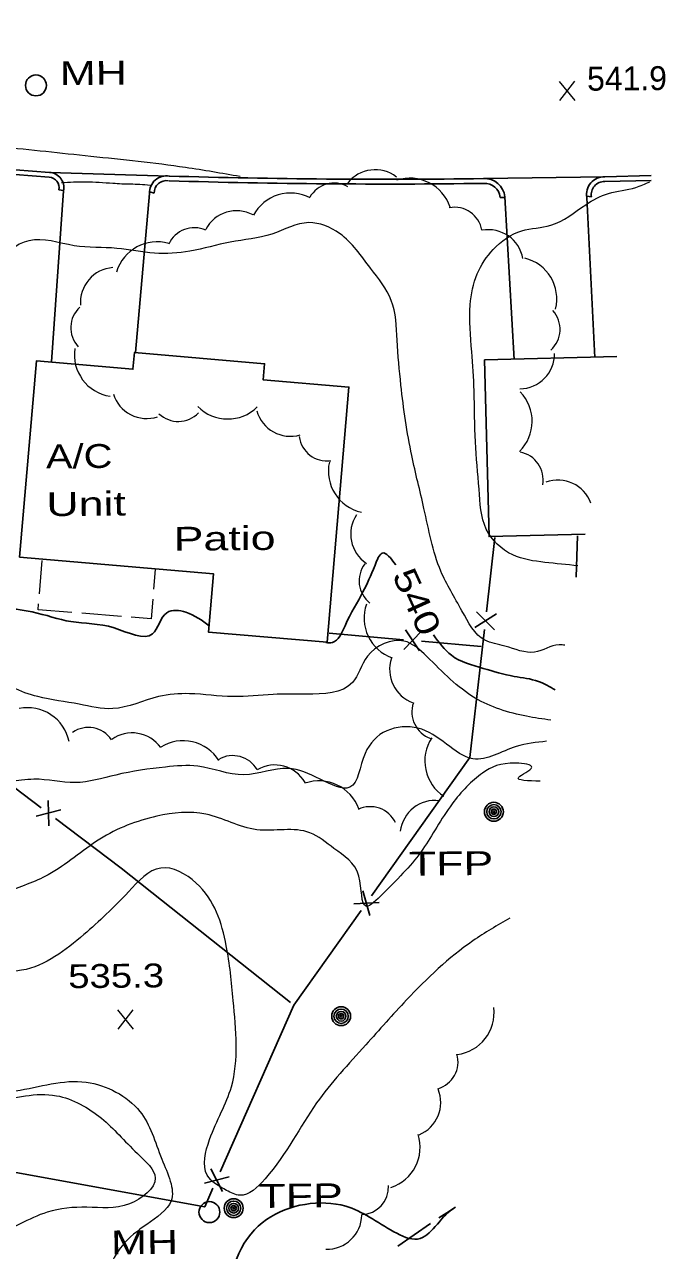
# Model space of a CAD drawing. Extents: x 2361708 to 2370558, y 6977955 to 6991887.
# Drawn here: x 2366752.4 to 2366881.3, y 6983523.9 to 6983770.4 of the extents above; entities that cross this region are included whole.
import ezdxf
from ezdxf.enums import TextEntityAlignment as Align

# ---------------------------------------------------------------- set-up
doc = ezdxf.new("R2010")
doc.units = 0
doc.header["$LTSCALE"] = 1.9
for name, color, linetype, lineweight in [('11', 7, 'Continuous', 25), ('12', 7, 'Continuous', 25), ('14', 7, 'Continuous', 13), ('17', 7, 'Continuous', 25), ('2', 7, 'Continuous', 25), ('20', 7, 'Continuous', 25), ('29', 7, 'Continuous', 13), ('31', 7, 'Continuous', 13), ('35', 7, 'Continuous', 13)]:
    doc.layers.add(name, color=color, linetype=linetype, lineweight=lineweight)

msp = doc.modelspace()

# ---------------------------------------------------------------- linework, layer by layer
at = {"layer": '11'}
msp.add_lwpolyline([(2366751.426, 6983663.277), (2366790.399, 6983659.958), (2366789.401, 6983648.238), (2366813.261, 6983646.205), (2366817.633, 6983697.479), (2366800.389, 6983698.955), (2366800.668, 6983702.167), (2366774.505, 6983704.419), (2366774.217, 6983701.066), (2366754.82, 6983702.731)], close=True, dxfattribs=at)
msp.add_lwpolyline([(2366871.488, 6983703.612), (2366844.893, 6983702.939), (2366845.801, 6983667.416), (2366865.107, 6983667.909)], dxfattribs=at)
at = {"layer": '12'}
msp.add_line((2366834.055, 6983529.327), (2366827.468, 6983524.784), dxfattribs=at)
msp.add_lwpolyline([(2366839.064, 6983532.635), (2366837.294, 6983531.498), (2366835.704, 6983530.463)], dxfattribs=at)
at = {"layer": '14'}
for p, q in [((2366755.416, 6983655.914), (2366755.942, 6983662.62)), ((2366778.691, 6983660.817), (2366778.378, 6983656.833)), ((2366771.88, 6983651.381), (2366763.904, 6983652.015))]:
    msp.add_line(p, q, dxfattribs=at)
for points in [[(2366761.912, 6983652.177), (2366755.157, 6983652.702), (2366755.255, 6983653.923)], [(2366778.218, 6983654.842), (2366777.905, 6983650.898), (2366773.872, 6983651.22)]]:
    msp.add_lwpolyline(points, dxfattribs=at)
at = {"layer": '17'}
for p, q in [((2366846.963, 6983667.206), (2366845.275, 6983652.3)), ((2366863.61, 6983667.595), (2366863.349, 6983659.282)), ((2366842.945, 6983649.147), (2366847.269, 6983651.878)), ((2366843.295, 6983652.321), (2366846.919, 6983648.695)), ((2366831.839, 6983644.431), (2366828.998, 6983648.695)), ((2366813.684, 6983647.989), (2366828.627, 6983646.691)), ((2366828.657, 6983644.711), (2366832.191, 6983648.415)), ((2366832.211, 6983646.375), (2366844.201, 6983645.329)), ((2366743.809, 6983621.933), (2366755.776, 6983612.886)), ((2366757.3, 6983609.27), (2366757.162, 6983614.389)), ((2366754.752, 6983611.196), (2366759.71, 6983612.463)), ((2366820.457, 6983596.191), (2366821.865, 6983591.264)), ((2366818.602, 6983593.583), (2366823.72, 6983593.872)), ((2366789.878, 6983540.327), (2366792.242, 6983535.789)), ((2366788.585, 6983537.405), (2366793.534, 6983538.712))]:
    msp.add_line(p, q, dxfattribs=at)
for points in [[(2366844.869, 6983648.726), (2366841.973, 6983623.037), (2366822.177, 6983595.207)], [(2366758.647, 6983610.713), (2366771.832, 6983600.758), (2366805.91, 6983573.761)], [(2366820.095, 6983592.277), (2366806.555, 6983573.247), (2366791.764, 6983539.725)], [(2366790.305, 6983536.431), (2366788.641, 6983532.655), (2366733.673, 6983542.672)]]:
    msp.add_lwpolyline(points, dxfattribs=at)
at = {"layer": '2'}
for p, q in [((2366781.528, 6983739.897), (2366757.45, 6983740.638)), ((2366869.094, 6983739.771), (2366844.666, 6983739.378)), ((2366878.402, 6983739.989), (2366869.094, 6983739.771)), ((2366878.411, 6983739.03), (2366869.112, 6983738.811)), ((2366760.255, 6983736.935), (2366757.812, 6983702.549)), ((2366759.313, 6983737.135), (2366760.255, 6983736.975)), ((2366777.541, 6983736.419), (2366774.746, 6983704.401)), ((2366778.501, 6983736.458), (2366777.588, 6983736.749)), ((2366848.012, 6983735.62), (2366848.972, 6983735.589)), ((2366848.971, 6983735.699), (2366850.823, 6983703.025)), ((2366866.392, 6983735.725), (2366865.441, 6983735.846)), ((2366865.443, 6983735.566), (2366867.039, 6983703.4))]:
    msp.add_line(p, q, dxfattribs=at)
for centre, radius, start, end in [((2366836.933, 6984859.981), 1123.122, 260.32788, 265.93829), ((2366836.933, 6984859.981), 1122.162, 260.32788, 265.93829), ((2366757.244, 6983737.567), 2.117, 348.14792, 86.15841), ((2366757.244, 6983737.567), 3.077, 348.14792, 86.15841), ((2366780.942, 6983736.544), 3.404, 80.07877, 182.1094), ((2366825.43, 6985239.846), 1500.591, 268.32349, 270.73449), ((2366869.006, 6983736.16), 3.612, 88.6053, 189.46421), ((2366780.942, 6983736.544), 2.444, 80.07877, 182.1094), ((2366825.43, 6985239.846), 1501.551, 268.32349, 270.73449), ((2366844.975, 6983735.381), 4.009, 4.55432, 94.41329), ((2366844.975, 6983735.381), 3.049, 4.55432, 94.41329), ((2366869.006, 6983736.16), 2.652, 88.6053, 189.46421)]:
    msp.add_arc(centre, radius, start, end, dxfattribs=at)
at = {"layer": '20'}
for centre, radius in [((2366754.713, 6983758.123), 2.1), ((2366846.778, 6983612.102), 1.9), ((2366846.778, 6983612.102), 1.442), ((2366846.778, 6983612.102), 0.973), ((2366846.778, 6983612.102), 0.539), ((2366846.778, 6983612.102), 0.192), ((2366816.067, 6983570.998), 1.9), ((2366816.067, 6983570.998), 1.442), ((2366816.067, 6983570.998), 0.973), ((2366816.067, 6983570.998), 0.539), ((2366816.067, 6983570.998), 0.192), ((2366789.581, 6983531.614), 2.1), ((2366794.464, 6983532.4), 1.9), ((2366794.464, 6983532.4), 1.442), ((2366794.464, 6983532.4), 0.973), ((2366794.464, 6983532.4), 0.539), ((2366794.464, 6983532.4), 0.192)]:
    msp.add_circle(centre, radius, dxfattribs=at)
at = {"layer": '29'}
for centre, radius, start, end in [((2366822.916, 6983734.121), 7.055, 52.38833, 142.38833), ((2366814.665, 6983732.857), 5.638, 60.58889, 150.58889), ((2366829.91, 6983731.025), 8.462, 18.00387, 108.00387), ((2366805.882, 6983728.032), 8.462, 61.91748, 151.91748), ((2366795.078, 6983725.868), 7.055, 62.08292, 152.08292), ((2366838.837, 6983727.986), 5.638, 10.39823, 100.39823), ((2366786.541, 6983723.87), 5.638, 65.57129, 155.57129), ((2366845.679, 6983722.054), 7.055, 10.39823, 100.39823), ((2366779.04, 6983718.224), 8.462, 73.61468, 163.61468), ((2366850.974, 6983715.175), 8.462, 346.2323, 76.2323), ((2366770.697, 6983714.463), 7.055, 94.34818, 184.34818), ((2366767.354, 6983709.4), 5.638, 132.54214, 222.54214), ((2366854.446, 6983709.104), 5.638, 311.87807, 41.87807), ((2366770.897, 6983703.996), 8.462, 171.45439, 261.45439), ((2366851.928, 6983704.189), 7.055, 270.4573, 0.4573), ((2366776.993, 6983698.216), 7.055, 197.67282, 287.67282), ((2366846.008, 6983690.592), 8.462, 314.31729, 44.31729), ((2366793.279, 6983699.523), 8.462, 224.50512, 314.50512), ((2366783.329, 6983696.213), 5.638, 226.37091, 316.37091), ((2366805.897, 6983694.638), 7.055, 195.95919, 285.95919), ((2366813.231, 6983688.264), 5.638, 187.60075, 277.60075), ((2366851.05, 6983678.837), 5.638, 349.72468, 79.72468), ((2366821.966, 6983680.589), 8.462, 167.56341, 257.56341), ((2366859.634, 6983671.728), 7.055, 19.90738, 109.90738), ((2366825.053, 6983667.929), 7.055, 146.58476, 236.58476), ((2366825.317, 6983658.517), 5.638, 142.31188, 232.31188), ((2366829.142, 6983651.03), 8.462, 160.53118, 250.53118), ((2366832.877, 6983640.69), 7.055, 161.01121, 251.01121), ((2366835.927, 6983632.164), 5.638, 161.01121, 251.01121), ((2366753.077, 6983624.547), 8.462, 11.67391, 101.67391), ((2366765.255, 6983623.403), 5.638, 34.22923, 124.22923), ((2366774.051, 6983620.897), 7.055, 35.501, 125.501), ((2366784.303, 6983617.919), 8.462, 31.96373, 121.96373), ((2366841.354, 6983622.302), 8.462, 146.82001, 236.82001), ((2366794.284, 6983617.744), 5.638, 30.01109, 120.01109), ((2366802.72, 6983614.452), 7.055, 30.01109, 120.01109), ((2366811.617, 6983609.84), 8.462, 19.50571, 109.50571), ((2366834.97, 6983607.325), 7.055, 83.06463, 173.06463), ((2366821.911, 6983607.49), 5.638, 25.50781, 115.50781), ((2366838.362, 6983571.704), 8.462, 276.91624, 6.91624), ((2366833.936, 6983561.845), 5.638, 285.96986, 15.96986), ((2366829.037, 6983553.671), 7.055, 292.45055, 22.45055), ((2366823.476, 6983544.623), 8.462, 288.00847, 18.00847), ((2366819.983, 6983536.743), 5.638, 272.01675, 2.01675), ((2366813.182, 6983531.199), 7.055, 268.54102, 358.54102)]:
    msp.add_arc(centre, radius, start, end, dxfattribs=at)
at = {"layer": '31'}
for p, q in [((2366863.087, 6983755.094), (2366859.971, 6983758.944)), ((2366860.008, 6983755.065), (2366863.05, 6983758.974)), ((2366774.31, 6983568.41), (2366771.193, 6983572.26)), ((2366771.23, 6983568.381), (2366774.273, 6983572.29))]:
    msp.add_line(p, q, dxfattribs=at)
at = {"layer": '31', "lineweight": 25}
for points in [[(2366827.064, 6983661.747), (2366824.332, 6983664.101), (2366822.885, 6983661.677), (2366820.455, 6983656.304), (2366816.86, 6983649.499), (2366814.302, 6983646.135), (2366813.022, 6983646.102)], [(2366789.509, 6983649.489), (2366784.843, 6983652.215), (2366781.053, 6983652.118), (2366778.174, 6983647.881), (2366770.442, 6983649.067), (2366761.759, 6983650.334), (2366753.961, 6983652.261), (2366747.757, 6983653.612), (2366742.809, 6983656.604), (2366734.911, 6983659.47), (2366729.477, 6983655.687), (2366726.12, 6983647.985), (2366719.2, 6983644.82), (2366710.639, 6983643.758), (2366699.079, 6983642.658), (2366694.648, 6983643.885)], [(2366859.105, 6983636.6), (2366855.718, 6983638.308), (2366850.849, 6983639.322), (2366844.633, 6983640.923), (2366838.238, 6983643.552), (2366834.639, 6983647.658)], [(2366838.686, 6983532.361), (2366838.477, 6983532.229), (2366831.444, 6983526.202), (2366826.66, 6983527.676), (2366816.981, 6983532.805), (2366808.817, 6983533.177), (2366795.511, 6983523.29), (2366794.748, 6983515.153), (2366804.244, 6983513.522), (2366807.862, 6983511.667), (2366805.953, 6983508.329), (2366801.068, 6983503.632), (2366794.607, 6983495.26), (2366786.548, 6983487.793)]]:
    msp.add_spline(points, degree=3, dxfattribs=at)
at = {"layer": '35'}
for points in [[(2366795.74, 6983739.802), (2366784.772, 6983741.618), (2366765.76, 6983743.847), (2366747.59, 6983745.754), (2366728.399, 6983747.912), (2366712.125, 6983750.377), (2366697.94, 6983751.832), (2366682.366, 6983755.404), (2366671.397, 6983760.49), (2366665.82, 6983767.497), (2366668.009, 6983771.788), (2366673.177, 6983775.238), (2366681.905, 6983776.521), (2366694.687, 6983776.332), (2366708.267, 6983775.382), (2366723.293, 6983774.854), (2366736.776, 6983774.553), (2366754.313, 6983773.84), (2366769.582, 6983774.095), (2366778.547, 6983773.57), (2366782.742, 6983774.2), (2366781.845, 6983774.902), (2366780.078, 6983775.605), (2366775.42, 6983776.351), (2366772.614, 6983777.014), (2366770.831, 6983777.407)], [(2366759.849, 6983738.591), (2366764.678, 6983738.756), (2366770.191, 6983738.469), (2366773.713, 6983738.313), (2366775.593, 6983738.271), (2366777.675, 6983738.08)], [(2366863.668, 6983661.545), (2366857.021, 6983662.242), (2366850.556, 6983663.75), (2366845.257, 6983668.93), (2366843.8, 6983676.927), (2366843.05, 6983686.47), (2366842.802, 6983696.729), (2366842.317, 6983704.584), (2366842.027, 6983714.042), (2366843.448, 6983720.256), (2366846.652, 6983725.136), (2366852.376, 6983728.881), (2366858.216, 6983729.997), (2366865.247, 6983734.134), (2366869.795, 6983736.417), (2366875.294, 6983737.619), (2366878.123, 6983738.766)], [(2366861.07, 6983645.58), (2366859.889, 6983645.659), (2366854.963, 6983644.171), (2366849, 6983645.425), (2366844.99, 6983646.577), (2366840.363, 6983652.473), (2366836.117, 6983660.473), (2366832.726, 6983673.091), (2366830.266, 6983683.698), (2366828.1, 6983697.858), (2366827.334, 6983706.922), (2366826.158, 6983714.891), (2366821.966, 6983721.391), (2366815.77, 6983728.342), (2366809.598, 6983730.534), (2366802.16, 6983728.253), (2366793.785, 6983726.613), (2366785.672, 6983724.796), (2366778.545, 6983724.408), (2366770.996, 6983725.366), (2366762.41, 6983725.905), (2366753.29, 6983726.908), (2366746.93, 6983721.677), (2366745.677, 6983713.554), (2366744.422, 6983705.642), (2366739.441, 6983701.535), (2366734.206, 6983700.945), (2366732.347, 6983700.877)], [(2366858.233, 6983630.522), (2366853.315, 6983631.295), (2366843.03, 6983634.948), (2366833.3, 6983643.315), (2366828.7, 6983646.422), (2366821.359, 6983643.351), (2366818.339, 6983638.063), (2366809.061, 6983635.714), (2366802.371, 6983635.69), (2366794.315, 6983635.244), (2366785.589, 6983635.841), (2366779.374, 6983635.242), (2366770.166, 6983632.834), (2366763.418, 6983633.72), (2366755.073, 6983635.24), (2366745.884, 6983640.283), (2366740.135, 6983646.489), (2366736.095, 6983646.42), (2366734.954, 6983642.409), (2366733.616, 6983635.846)], [(2366857.373, 6983626.264), (2366851.233, 6983625.205), (2366842.576, 6983622.743), (2366837.258, 6983625.692), (2366831.507, 6983628.908), (2366825.222, 6983628.377), (2366820.885, 6983623.806), (2366817.819, 6983617.017), (2366811.873, 6983618.62), (2366805.433, 6983620.799), (2366796.524, 6983619.544), (2366787.238, 6983621.246), (2366780.769, 6983621.094), (2366770.764, 6983619.489), (2366762.608, 6983617.951), (2366754.291, 6983618.642), (2366751.833, 6983618.449), (2366747.317, 6983617.946)], [(2366856.109, 6983618.271), (2366851.762, 6983619.03), (2366854.403, 6983621.035), (2366851.205, 6983621.865), (2366844.494, 6983619.891), (2366838.372, 6983613.682), (2366832.489, 6983604.566), (2366824.444, 6983595.589), (2366821.117, 6983593.107), (2366819.619, 6983599.143), (2366814.626, 6983604.716), (2366809.776, 6983607.89), (2366799.139, 6983608.498), (2366788.859, 6983611.621), (2366779.023, 6983611.207), (2366767.556, 6983606.598), (2366757.154, 6983599.418), (2366748.506, 6983595.916), (2366741.955, 6983592.973), (2366735.284, 6983586.649), (2366731.169, 6983578.81), (2366727.22, 6983567.152), (2366724.1, 6983557.572), (2366725.878, 6983550.458), (2366730.435, 6983549.752), (2366738.912, 6983552.273), (2366746.238, 6983553.782), (2366758.837, 6983555.022), (2366767.87, 6983550.488), (2366775.108, 6983543.397), (2366778.695, 6983538.441), (2366773.514, 6983533.281), (2366764.97, 6983532.599), (2366757, 6983531.594), (2366745.884, 6983526.788), (2366738.094, 6983523.663), (2366735.44, 6983516.778), (2366733.791, 6983506.141), (2366731.129, 6983489.545), (2366730.226, 6983479.347), (2366728.915, 6983472.024), (2366723.34, 6983467.27), (2366720.422, 6983462.922), (2366715.728, 6983454.827), (2366714.266, 6983448.783), (2366713.154, 6983442.722), (2366713.501, 6983435.665), (2366715.14, 6983431.55), (2366713.102, 6983427.131), (2366708.793, 6983421.76), (2366701.925, 6983415.144), (2366693.925, 6983407.837), (2366686.4, 6983399.885), (2366674.93, 6983388.235), (2366666.489, 6983378.825), (2366656.269, 6983370.397), (2366646.079, 6983365.1), (2366633.827, 6983356.873), (2366622.736, 6983348.407), (2366608.181, 6983338.438), (2366596.544, 6983332.746), (2366582.343, 6983324.421), (2366569.752, 6983320.291), (2366554.555, 6983315.656), (2366546.007, 6983314.345), (2366534.798, 6983313.128), (2366523.363, 6983313.629), (2366513.723, 6983314.658), (2366504.199, 6983317.077), (2366493.114, 6983317.561), (2366483.21, 6983320.008), (2366474.457, 6983322.414), (2366465.519, 6983324.299), (2366452.712, 6983327.028), (2366440.705, 6983330.853), (2366428.092, 6983333.163), (2366420.094, 6983336.057), (2366410.051, 6983339.502), (2366403.905, 6983342.184), (2366394.662, 6983345.686), (2366386.599, 6983349.099), (2366379.907, 6983351.305), (2366374.743, 6983352.796), (2366369.4, 6983355.226), (2366369.309, 6983355.285)], [(2366850.011, 6983590.732), (2366842.564, 6983586.151), (2366829.217, 6983574.273), (2366821.002, 6983565.214), (2366811.143, 6983553.56), (2366800.768, 6983538.3), (2366795.699, 6983534.992), (2366793.05, 6983535.977), (2366789.15, 6983539.04), (2366789.632, 6983546.235), (2366794.001, 6983556.797), (2366794.376, 6983574.142), (2366792.981, 6983585.168), (2366786.941, 6983597.772), (2366779.802, 6983600.794), (2366773.317, 6983596.012), (2366764.329, 6983587.406), (2366751.826, 6983580.227), (2366742.62, 6983578.759), (2366736.872, 6983566.964), (2366742.523, 6983556.397), (2366750.597, 6983555.964), (2366764.831, 6983557.73), (2366775.587, 6983551.872), (2366780.029, 6983542.243), (2366781.879, 6983533.851), (2366776.994, 6983529.154), (2366772.094, 6983524.907), (2366769.102, 6983519.858), (2366765.94, 6983510.598), (2366763.04, 6983499.01), (2366755.53, 6983493.738), (2366748.134, 6983486.897), (2366742.514, 6983476.433), (2366736.503, 6983468.115), (2366730.644, 6983456.459), (2366731.555, 6983450.008), (2366731.285, 6983444.715), (2366725.708, 6983438.041), (2366719.435, 6983432.011), (2366713.06, 6983424.2), (2366704.213, 6983414.386), (2366696.871, 6983407.105), (2366688.755, 6983399.368), (2366677.579, 6983387.281), (2366666.505, 6983376.085), (2366656.537, 6983368.52), (2366641.854, 6983358.199), (2366628.954, 6983349.806), (2366615.085, 6983340.173), (2366605.513, 6983335.072), (2366604.687, 6983334.604)]]:
    msp.add_spline(points, degree=3, dxfattribs=at)

# ---------------------------------------------------------------- texts
at = {"layer": '14', "width": 1.4}
msp.add_text('Patio', height=4.8, rotation=0.545, dxfattribs=at).set_placement((2366782.415, 6983664.562))
at = {"layer": '20'}
for s, width, p in [('  MH', 1.35, (2366754.713, 6983758.123)), ('A/C', 1.25, (2366756.736, 6983681.118)), ('Unit', 1.4, (2366756.828, 6983671.519)), ('  TFP', 1.4, (2366824.709, 6983599.191)), ('  TFP', 1.4, (2366794.464, 6983532.4)), ('  MH', 1.35, (2366765.011, 6983523.06))]:
    msp.add_text(s, height=4.8, rotation=0.545, dxfattribs=dict(at, width=width)).set_placement(p)
at = {"layer": '31'}
msp.add_text('541.9', height=4.8, rotation=0.545, dxfattribs=at).set_placement((2366865.529, 6983757.057))
at = {"layer": '31', "width": 1.3}
msp.add_text(' 540 ', height=4.8, rotation=294.425, dxfattribs=at).set_placement((2366829.13, 6983653.349), align=Align.CENTER)
at = {"layer": '31', "width": 1.2}
msp.add_text('535.3', height=4.8, rotation=0.545, dxfattribs=at).set_placement((2366761.221, 6983576.626))

doc.saveas('drawing.dxf')
